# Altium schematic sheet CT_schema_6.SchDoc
size 310 x 315 mm
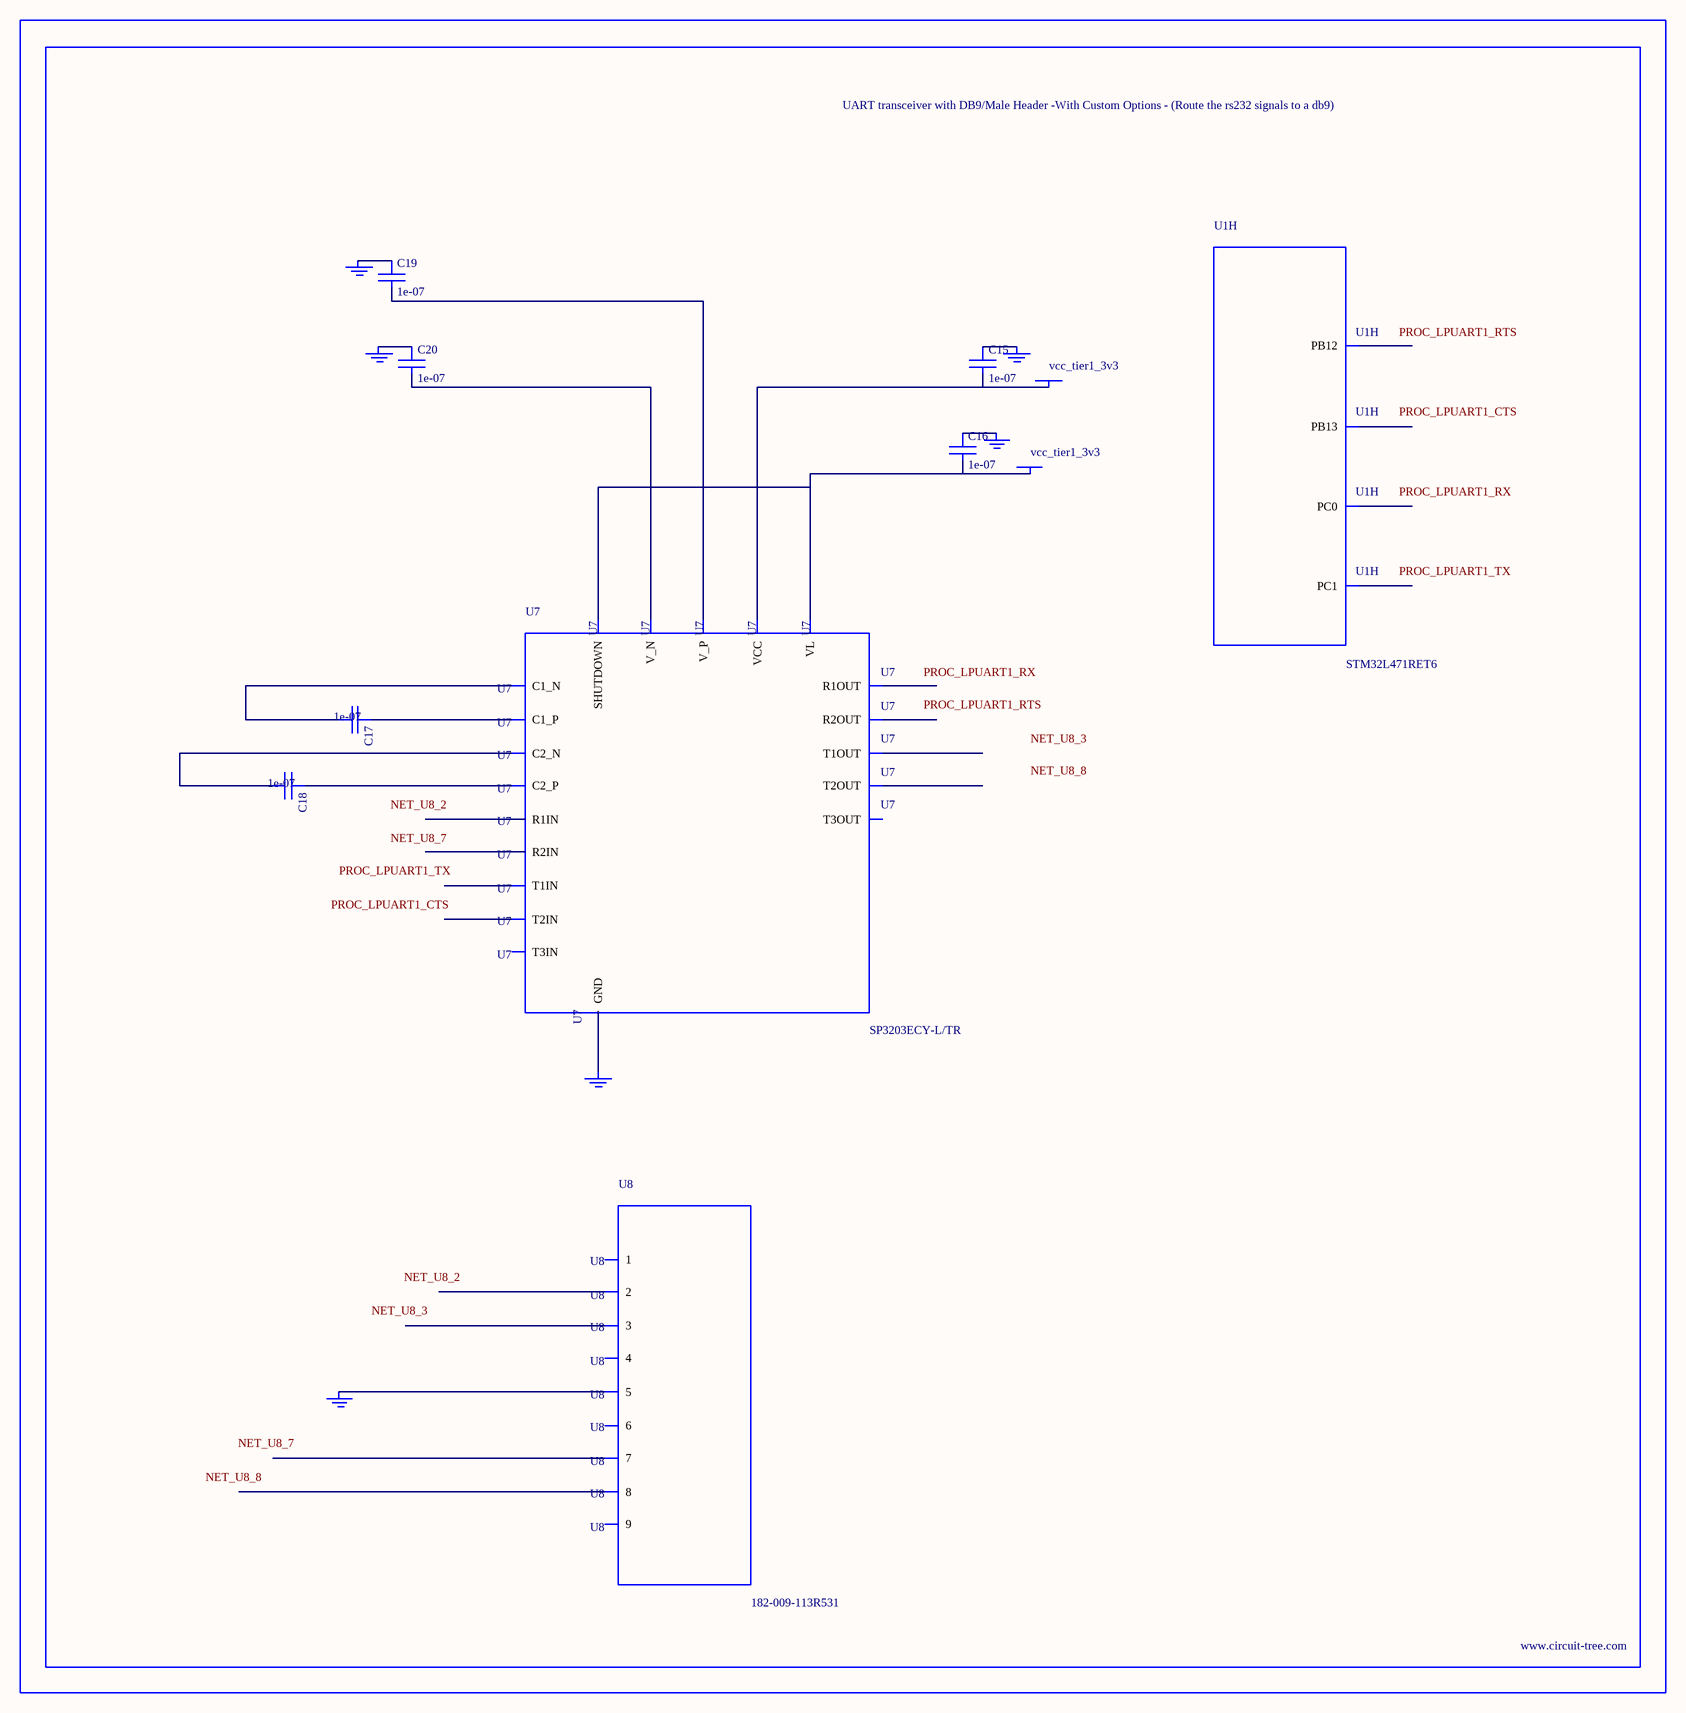
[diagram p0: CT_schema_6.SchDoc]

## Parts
BORDER5  (no value)
C15  1e-07  [C0402]
C16  1e-07  [C0402]
C17  1e-07  [C0402]
C18  1e-07  [C0402]
C19  1e-07  [C0402]
C20  1e-07  [C0402]
GND_INSTANCE_5_0  (no value)
GND_INSTANCE_5_1  (no value)
GND_INSTANCE_5_2  (no value)
GND_INSTANCE_5_3  (no value)
GND_INSTANCE_5_4  (no value)
GND_INSTANCE_5_5  (no value)
POWER_INSTANCE_5_0  vcc_tier1_3v3
POWER_INSTANCE_5_1  vcc_tier1_3v3
U1  STM32L471RET6  [LQFP64]  (part H of 8)
U7  SP3203ECY-L/TR  [TSSOP20-I]
U8  182-009-113R531  [182-009-MALE]

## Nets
NetC15_1: C15.1 GND_INSTANCE_5_3.0(GND)
NetC15_2: C15.2 POWER_INSTANCE_5_1.0(PWR) U7.19(VCC)
NetC16_1: C16.1 GND_INSTANCE_5_2.0(GND)
NetC16_2: C16.2 POWER_INSTANCE_5_0.0(PWR) U7.12(VL) U7.20(SHUTDOWN)
NetC17_1: C17.1 U7.1(C1_P)
NetC17_2: C17.2 U7.3(C1_N)
NetC18_1: C18.1 U7.4(C2_P)
NetC18_2: C18.2 U7.5(C2_N)
NetC19_1: C19.1 GND_INSTANCE_5_0.0(GND)
NetC19_2: C19.2 U7.2(V_P)
NetC20_1: C20.1 GND_INSTANCE_5_1.0(GND)
NetC20_2: C20.2 U7.6(V_N)
NetGND_INSTANCE_5_4_0: GND_INSTANCE_5_4.0(GND) U7.18(GND)
NetGND_INSTANCE_5_5_0: GND_INSTANCE_5_5.0(GND) U8.5

Not connected (* = marked no-connect by the designer): U1 8(PC0) 9(PC1) 33(PB12) 34(PB13); U7 7(T1IN) 8(T2IN) 9(T3IN) 10(R2OUT) 11(R1OUT) 13(R2IN) 14(R1IN) 15(T3OUT) 16(T2OUT) 17(T1OUT); U8 1 2 3 4 6 7 8 9

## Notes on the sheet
- Labels drawn without touching a wire or pin: NET_U8_2, NET_U8_3, NET_U8_7, NET_U8_8, PROC_LPUART1_CTS, PROC_LPUART1_RTS, PROC_LPUART1_RX, PROC_LPUART1_TX

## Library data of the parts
BORDER5 = BORDER_PAGE5
C15-C20 = C0402C104K3RACTU
GND_INSTANCE_5_0-GND_INSTANCE_5_5 = GND
POWER_INSTANCE_5_0 POWER_INSTANCE_5_1 = PWR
